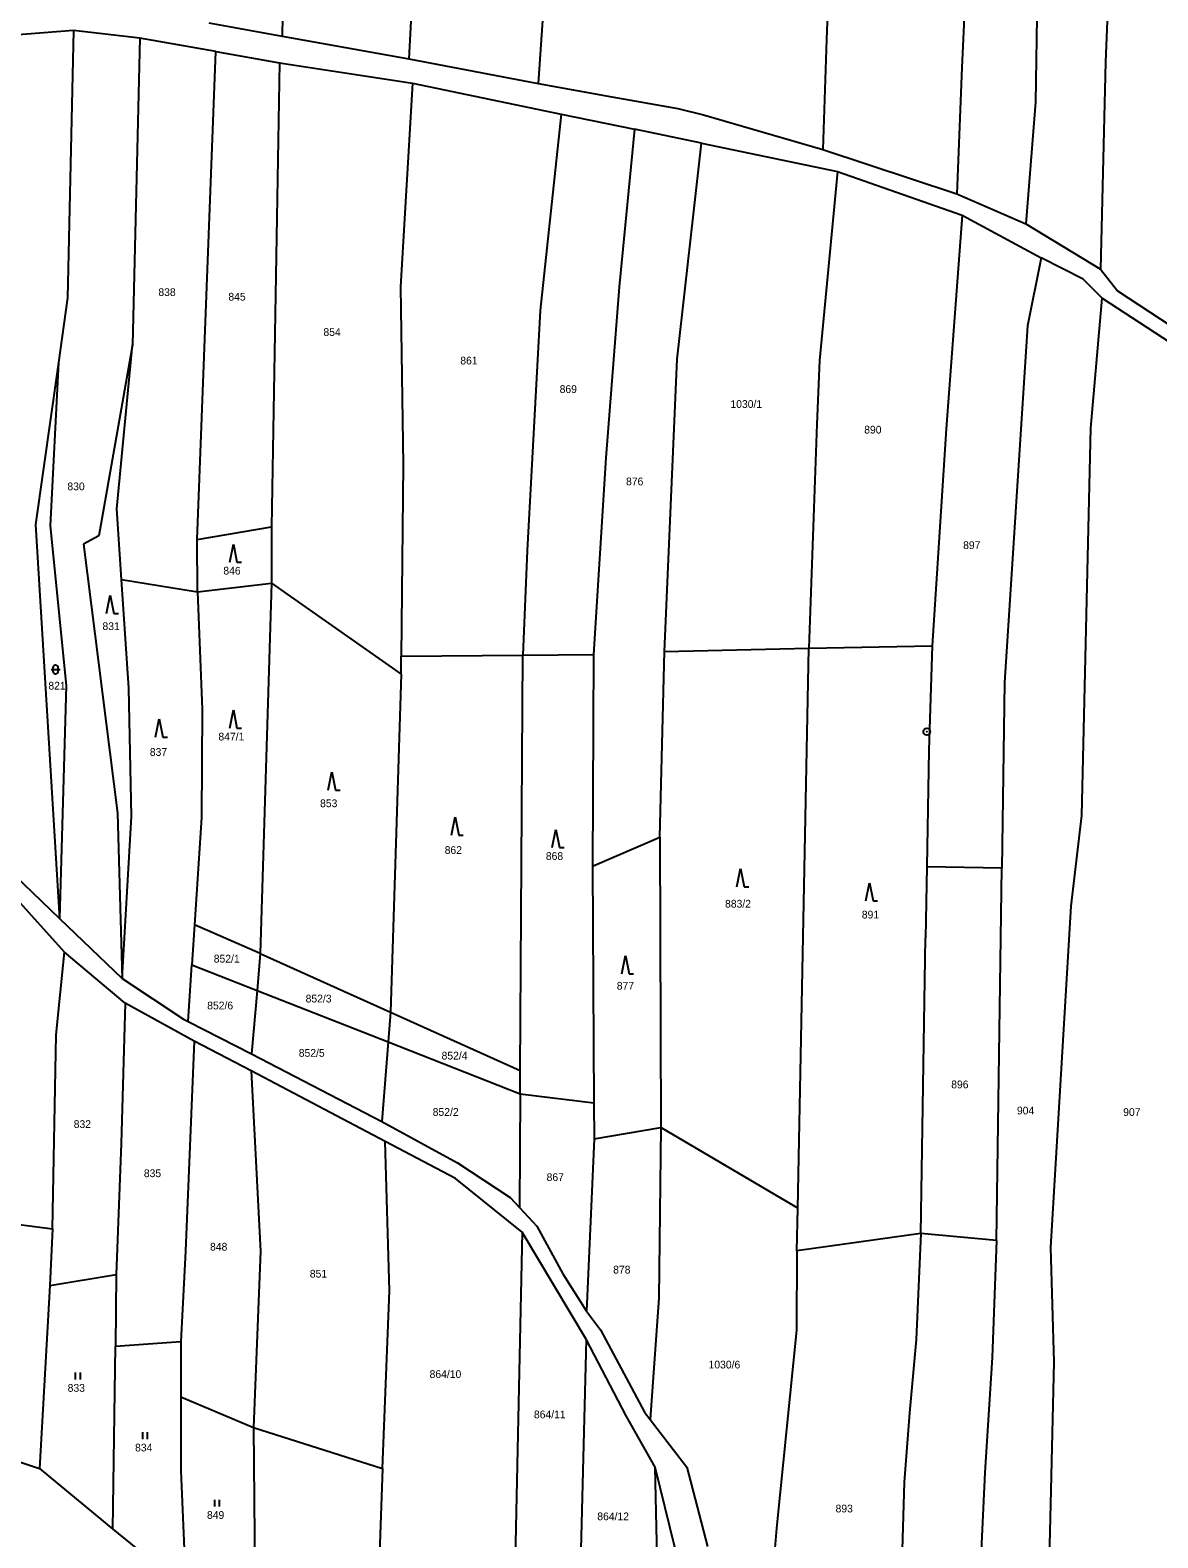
# Model space of a CAD drawing. Extents: x -794142 to -791199, y -1109267 to -1105626.
# Drawn here: x -792888.4 to -792641, y -1108421 to -1108090.1 of the extents above; entities that cross this region are included whole.
import ezdxf

# ---------------------------------------------------------------- set-up
doc = ezdxf.new("R2010")
doc.units = 0
for name, color, linetype in [('Vrstva 1', 7, 'Continuous'), ('Vrstva 14', 7, 'Continuous'), ('Vrstva 23', 7, 'Continuous'), ('Vrstva 28', 7, 'Continuous')]:
    doc.layers.add(name, color=color, linetype=linetype)

msp = doc.modelspace()

# ---------------------------------------------------------------- linework, layer by layer
at = {"layer": 'Vrstva 1'}
for p, q in [((-792665.55, -1107962.36), (-792667.85, -1108105.9)), ((-792830.62, -1107984.08), (-792833.11, -1108091.41)), ((-792710.18, -1107997.92), (-792713.64, -1108092.18)), ((-792800.6, -1108011.76), (-792805.3, -1108096.41)), ((-792771.61, -1108024.99), (-792776.93, -1108101.83)), ((-792680.74, -1108026.56), (-792683.96, -1108098.3)), ((-792650.37, -1108043.61), (-792652.44, -1108097.13)), ((-792849.16, -1108088.53), (-792833.11, -1108091.41)), ((-792878.82, -1108090.18), (-792895.65, -1108091.52)), ((-792878.82, -1108090.18), (-792880.16, -1108148.89)), ((-792864.29, -1108091.85), (-792878.82, -1108090.18)), ((-792864.29, -1108091.85), (-792865.89, -1108159.21)), ((-792847.61, -1108094.83), (-792864.29, -1108091.85)), ((-792833.11, -1108091.41), (-792805.3, -1108096.41)), ((-792851.73, -1108201.91), (-792847.61, -1108094.83)), ((-792847.61, -1108094.83), (-792833.66, -1108097.29)), ((-792713.64, -1108092.18), (-792714.47, -1108116.28)), ((-792833.66, -1108097.29), (-792835.42, -1108199.14)), ((-792833.66, -1108097.29), (-792804.47, -1108101.76)), ((-792805.3, -1108096.41), (-792776.93, -1108101.83)), ((-792683.96, -1108098.3), (-792685.05, -1108126.02)), ((-792652.44, -1108097.13), (-792653.58, -1108142.57)), ((-792804.47, -1108101.76), (-792807.15, -1108146.46)), ((-792804.47, -1108101.76), (-792771.85, -1108108.59)), ((-792776.93, -1108101.83), (-792760.74, -1108104.79)), ((-792760.74, -1108104.79), (-792746.3, -1108107.33)), ((-792771.85, -1108108.59), (-792776.47, -1108151.65)), ((-792771.85, -1108108.59), (-792755.77, -1108111.87)), ((-792746.3, -1108107.33), (-792740.64, -1108108.73)), ((-792667.85, -1108105.9), (-792669.96, -1108132.59)), ((-792755.77, -1108111.87), (-792759.12, -1108146.43)), ((-792741.09, -1108114.9), (-792755.77, -1108111.87)), ((-792740.64, -1108108.73), (-792714.47, -1108116.28)), ((-792746.46, -1108162.29), (-792741.09, -1108114.9)), ((-792741.09, -1108114.9), (-792711.24, -1108121.16)), ((-792714.47, -1108116.28), (-792685.05, -1108126.02)), ((-792711.24, -1108121.16), (-792715.18, -1108162.59)), ((-792711.24, -1108121.16), (-792683.91, -1108130.73)), ((-792685.05, -1108126.02), (-792669.96, -1108132.59)), ((-792683.91, -1108130.73), (-792687.41, -1108177.63)), ((-792683.91, -1108130.73), (-792666.56, -1108140.08)), ((-792669.96, -1108132.59), (-792653.58, -1108142.57)), ((-792666.56, -1108140.08), (-792669.54, -1108154.98)), ((-792657.33, -1108144.76), (-792666.56, -1108140.08)), ((-792653.17, -1108148.97), (-792657.33, -1108144.76)), ((-792653.58, -1108142.57), (-792649.81, -1108147.33)), ((-792807.15, -1108146.46), (-792806.55, -1108185.5)), ((-792759.12, -1108146.43), (-792762.1, -1108183.98)), ((-792649.81, -1108147.33), (-792628.98, -1108161.01)), ((-792880.16, -1108148.89), (-792882.16, -1108163.04)), ((-792776.47, -1108151.65), (-792779.3, -1108204.34)), ((-792655.7, -1108177.43), (-792653.17, -1108148.97)), ((-792653.17, -1108148.97), (-792626.61, -1108166.32)), ((-792669.54, -1108154.98), (-792674.6, -1108233.26)), ((-792865.89, -1108159.21), (-792873.27, -1108201.08)), ((-792869.37, -1108195.13), (-792865.89, -1108159.21)), ((-792882.16, -1108163.04), (-792887.22, -1108198.63)), ((-792882.16, -1108163.04), (-792884, -1108198.88)), ((-792749.22, -1108226.49), (-792746.46, -1108162.29)), ((-792715.18, -1108162.59), (-792715.77, -1108176.59)), ((-792715.77, -1108176.59), (-792717.52, -1108225.72)), ((-792687.41, -1108177.63), (-792690.5, -1108225.21)), ((-792657.64, -1108262.42), (-792655.7, -1108177.43)), ((-792762.1, -1108183.98), (-792764.81, -1108227.16)), ((-792806.55, -1108185.5), (-792806.94, -1108227.47)), ((-792868.32, -1108210.68), (-792869.37, -1108195.13)), ((-792887.22, -1108198.63), (-792881.96, -1108285.08)), ((-792884, -1108198.88), (-792880.45, -1108233.94)), ((-792873.27, -1108201.08), (-792876.63, -1108202.92)), ((-792851.73, -1108201.91), (-792835.42, -1108199.14)), ((-792835.42, -1108199.14), (-792835.42, -1108211.46)), ((-792876.63, -1108202.92), (-792869.23, -1108261.95)), ((-792851.65, -1108213.34), (-792851.73, -1108201.91)), ((-792779.3, -1108204.34), (-792780.3, -1108227.26)), ((-792866.7, -1108234.53), (-792868.32, -1108210.68)), ((-792868.32, -1108210.68), (-792851.65, -1108213.34)), ((-792851.65, -1108213.34), (-792835.42, -1108211.46)), ((-792851.65, -1108213.34), (-792850.66, -1108239.1)), ((-792835.42, -1108211.46), (-792837.88, -1108292.76)), ((-792835.42, -1108211.46), (-792806.94, -1108231.47)), ((-792806.94, -1108227.47), (-792780.3, -1108227.26)), ((-792806.94, -1108231.47), (-792806.94, -1108227.47)), ((-792780.86, -1108318.38), (-792780.3, -1108227.26)), ((-792780.3, -1108227.26), (-792764.81, -1108227.16)), ((-792764.81, -1108227.16), (-792765.01, -1108273.59)), ((-792750.24, -1108267.23), (-792749.22, -1108226.49)), ((-792749.22, -1108226.49), (-792717.52, -1108225.72)), ((-792719.95, -1108348.6), (-792717.52, -1108225.72)), ((-792717.52, -1108225.72), (-792690.5, -1108225.21)), ((-792690.5, -1108225.21), (-792691.22, -1108248.15)), ((-792880.45, -1108233.94), (-792881.96, -1108285.08)), ((-792806.94, -1108231.47), (-792809.35, -1108305.58)), ((-792674.6, -1108233.26), (-792675.2, -1108274.03)), ((-792866.15, -1108262.65), (-792866.7, -1108234.53)), ((-792850.66, -1108239.1), (-792850.8, -1108262.92)), ((-792691.22, -1108248.15), (-792691.67, -1108273.69)), ((-792869.23, -1108261.95), (-792868.2, -1108298.19)), ((-792868.2, -1108298.19), (-792866.15, -1108262.65)), ((-792850.8, -1108262.92), (-792852.32, -1108286.45)), ((-792660.01, -1108282.35), (-792657.64, -1108262.42)), ((-792765.01, -1108273.59), (-792750.24, -1108267.23)), ((-792750.24, -1108267.23), (-792750.02, -1108330.95)), ((-792899.4, -1108268.29), (-792881.96, -1108285.08)), ((-792880.81, -1108292.42), (-792897.89, -1108273.53)), ((-792765.01, -1108273.59), (-792764.68, -1108325.53)), ((-792691.67, -1108273.69), (-792691.94, -1108289.27)), ((-792675.2, -1108274.03), (-792691.67, -1108273.69)), ((-792676.41, -1108355.7), (-792675.2, -1108274.03)), ((-792664.48, -1108357.27), (-792660.01, -1108282.35)), ((-792881.96, -1108285.08), (-792868.2, -1108298.19)), ((-792852.32, -1108286.45), (-792852.88, -1108295.2)), ((-792837.88, -1108292.76), (-792852.32, -1108286.45)), ((-792693, -1108354.18), (-792691.94, -1108289.27)), ((-792882.68, -1108310.58), (-792880.81, -1108292.42)), ((-792867.54, -1108303.62), (-792880.81, -1108292.42)), ((-792837.88, -1108292.76), (-792838.58, -1108300.83)), ((-792837.88, -1108292.76), (-792809.35, -1108305.58)), ((-792853.68, -1108307.68), (-792852.88, -1108295.2)), ((-792852.88, -1108295.2), (-792838.58, -1108300.83)), ((-792868.2, -1108298.19), (-792854.7, -1108307.16)), ((-792867.54, -1108303.62), (-792868.37, -1108334.44)), ((-792852.42, -1108311.98), (-792867.54, -1108303.62)), ((-792838.58, -1108300.83), (-792839.78, -1108314.72)), ((-792838.58, -1108300.83), (-792809.86, -1108312.13)), ((-792854.7, -1108307.16), (-792853.68, -1108307.68)), ((-792809.35, -1108305.58), (-792809.86, -1108312.13)), ((-792809.35, -1108305.58), (-792780.86, -1108318.38)), ((-792853.68, -1108307.68), (-792839.78, -1108314.72)), ((-792883.44, -1108353.15), (-792882.68, -1108310.58)), ((-792852.42, -1108311.98), (-792854.26, -1108358.09)), ((-792839.89, -1108318.51), (-792852.42, -1108311.98)), ((-792809.86, -1108312.13), (-792811.23, -1108329.63)), ((-792809.86, -1108312.13), (-792780.89, -1108323.53)), ((-792839.78, -1108314.72), (-792811.23, -1108329.63)), ((-792839.89, -1108318.51), (-792837.84, -1108358.03)), ((-792810.51, -1108334), (-792839.89, -1108318.51)), ((-792780.89, -1108323.53), (-792780.86, -1108318.38)), ((-792780.89, -1108323.53), (-792781.04, -1108348.46)), ((-792780.89, -1108323.53), (-792764.68, -1108325.53)), ((-792764.68, -1108325.53), (-792764.63, -1108333.43)), ((-792811.23, -1108329.63), (-792794.61, -1108338.65)), ((-792764.63, -1108333.43), (-792766.34, -1108371.22)), ((-792764.63, -1108333.43), (-792750.02, -1108330.95)), ((-792750.02, -1108330.95), (-792750.48, -1108368.33)), ((-792719.95, -1108348.6), (-792750.02, -1108330.95)), ((-792868.37, -1108334.44), (-792869.52, -1108363.21)), ((-792809.53, -1108366.78), (-792810.51, -1108334)), ((-792795.05, -1108342.12), (-792810.51, -1108334)), ((-792794.61, -1108338.65), (-792783.07, -1108346.3)), ((-792780.44, -1108353.88), (-792795.05, -1108342.12)), ((-792783.07, -1108346.3), (-792781.04, -1108348.46)), ((-792781.04, -1108348.46), (-792777.19, -1108352.57)), ((-792720.14, -1108358.01), (-792719.95, -1108348.6)), ((-792901.5, -1108350.78), (-792883.44, -1108353.15)), ((-792883.44, -1108353.15), (-792884.03, -1108365.58)), ((-792777.19, -1108352.57), (-792771.5, -1108363.03)), ((-792780.44, -1108353.88), (-792781.94, -1108425.49)), ((-792766.34, -1108377.52), (-792780.44, -1108353.88)), ((-792693, -1108354.18), (-792720.14, -1108358.01)), ((-792693, -1108354.18), (-792693.97, -1108377.44)), ((-792676.41, -1108355.7), (-792693, -1108354.18)), ((-792676.41, -1108355.7), (-792677.29, -1108381.38)), ((-792854.26, -1108358.09), (-792855.32, -1108377.87)), ((-792837.84, -1108358.03), (-792839.37, -1108396.76)), ((-792720.14, -1108358.01), (-792720.26, -1108375.38)), ((-792663.74, -1108382.44), (-792664.48, -1108357.27)), ((-792884.03, -1108365.58), (-792869.52, -1108363.21)), ((-792869.52, -1108363.21), (-792869.67, -1108378.91)), ((-792771.5, -1108363.03), (-792766.34, -1108371.22)), ((-792884.03, -1108365.58), (-792886.32, -1108405.71)), ((-792811.1, -1108405.72), (-792809.53, -1108366.78)), ((-792750.48, -1108368.33), (-792752.37, -1108394.99)), ((-792766.34, -1108371.22), (-792763.25, -1108375.3)), ((-792763.25, -1108375.3), (-792753.62, -1108393.36)), ((-792720.26, -1108375.38), (-792724.65, -1108418.81)), ((-792870.21, -1108419.08), (-792869.67, -1108378.91)), ((-792869.67, -1108378.91), (-792855.32, -1108377.87)), ((-792855.32, -1108377.87), (-792855.32, -1108390.02)), ((-792767.58, -1108426.45), (-792766.34, -1108377.52)), ((-792757.64, -1108394.2), (-792766.34, -1108377.52)), ((-792693.97, -1108377.44), (-792695.46, -1108393.53)), ((-792677.29, -1108381.38), (-792678.93, -1108406.65)), ((-792664.48, -1108413.59), (-792663.74, -1108382.44)), ((-792855.32, -1108390.02), (-792855.33, -1108406.24)), ((-792855.32, -1108390.02), (-792839.37, -1108396.76)), ((-792751.22, -1108405.47), (-792757.64, -1108394.2)), ((-792753.62, -1108393.36), (-792752.37, -1108394.99)), ((-792752.37, -1108394.99), (-792744.34, -1108405.47)), ((-792695.46, -1108393.53), (-792696.65, -1108408.73)), ((-792839.37, -1108396.76), (-792838.98, -1108444.42)), ((-792839.37, -1108396.76), (-792811.1, -1108405.72)), ((-792903.82, -1108400.01), (-792886.32, -1108405.71)), ((-792886.32, -1108405.71), (-792870.21, -1108419.08)), ((-792855.33, -1108406.24), (-792854.24, -1108432)), ((-792811.1, -1108405.72), (-792811.91, -1108429.71)), ((-792750.3, -1108447.92), (-792751.22, -1108405.47)), ((-792745.94, -1108427.17), (-792751.22, -1108405.47)), ((-792744.34, -1108405.47), (-792739.76, -1108422.84)), ((-792696.65, -1108408.73), (-792697.7, -1108444.29)), ((-792678.93, -1108406.65), (-792680.27, -1108435.34)), ((-792665.97, -1108475.58), (-792664.48, -1108413.59)), ((-792870.21, -1108419.08), (-792854.24, -1108432)), ((-792724.65, -1108418.81), (-792727.1, -1108448.02))]:
    msp.add_line(p, q, dxfattribs=at)
at = {"layer": 'Vrstva 23'}
for p, q in [((-792844.59, -1108206.88), (-792843.79, -1108202.88)), ((-792843.79, -1108202.88), (-792842.99, -1108206.88)), ((-792842.99, -1108206.88), (-792841.99, -1108206.88)), ((-792871.6, -1108218.12), (-792870.8, -1108214.12)), ((-792870.8, -1108214.12), (-792870, -1108218.12)), ((-792870, -1108218.12), (-792869, -1108218.12)), ((-792883.79, -1108230.41), (-792881.79, -1108230.41)), ((-792883.29, -1108229.81), (-792883.19, -1108229.61)), ((-792883.29, -1108231.01), (-792883.29, -1108229.81)), ((-792883.19, -1108231.21), (-792883.29, -1108231.01)), ((-792883.19, -1108229.61), (-792883.09, -1108229.51)), ((-792883.09, -1108229.51), (-792882.89, -1108229.41)), ((-792882.89, -1108229.41), (-792882.69, -1108229.41)), ((-792882.69, -1108229.41), (-792882.49, -1108229.51)), ((-792882.49, -1108229.51), (-792882.39, -1108229.61)), ((-792882.39, -1108229.61), (-792882.29, -1108229.81)), ((-792882.29, -1108231.01), (-792882.39, -1108231.21)), ((-792882.29, -1108229.81), (-792882.29, -1108231.01)), ((-792883.09, -1108231.31), (-792883.19, -1108231.21)), ((-792882.89, -1108231.41), (-792883.09, -1108231.31)), ((-792882.69, -1108231.41), (-792882.89, -1108231.41)), ((-792882.49, -1108231.31), (-792882.69, -1108231.41)), ((-792882.39, -1108231.21), (-792882.49, -1108231.31)), ((-792844.59, -1108243.29), (-792843.79, -1108239.29)), ((-792843.79, -1108239.29), (-792842.99, -1108243.29)), ((-792860.85, -1108245.24), (-792860.05, -1108241.24)), ((-792860.05, -1108241.24), (-792859.25, -1108245.24)), ((-792842.99, -1108243.29), (-792841.99, -1108243.29)), ((-792859.25, -1108245.24), (-792858.25, -1108245.24)), ((-792822.99, -1108256.86), (-792822.19, -1108252.86)), ((-792822.19, -1108252.86), (-792821.39, -1108256.86)), ((-792821.39, -1108256.86), (-792820.39, -1108256.86)), ((-792795.95, -1108266.77), (-792795.15, -1108262.77)), ((-792795.15, -1108262.77), (-792794.35, -1108266.77)), ((-792794.35, -1108266.77), (-792793.35, -1108266.77)), ((-792773.84, -1108269.5), (-792773.04, -1108265.5)), ((-792773.04, -1108265.5), (-792772.24, -1108269.5)), ((-792772.24, -1108269.5), (-792771.24, -1108269.5)), ((-792733.33, -1108278.11), (-792732.53, -1108274.11)), ((-792732.53, -1108274.11), (-792731.73, -1108278.11)), ((-792705.05, -1108281.21), (-792704.25, -1108277.21)), ((-792704.25, -1108277.21), (-792703.45, -1108281.21)), ((-792731.73, -1108278.11), (-792730.73, -1108278.11)), ((-792703.45, -1108281.21), (-792702.45, -1108281.21)), ((-792758.59, -1108297.19), (-792757.79, -1108293.19)), ((-792757.79, -1108293.19), (-792756.99, -1108297.19)), ((-792756.99, -1108297.19), (-792755.99, -1108297.19)), ((-792878.42, -1108386.21), (-792878.42, -1108384.71)), ((-792877.42, -1108384.71), (-792877.42, -1108386.21)), ((-792863.66, -1108399.3), (-792863.66, -1108397.8)), ((-792862.66, -1108397.8), (-792862.66, -1108399.3)), ((-792847.88, -1108414.1), (-792847.88, -1108412.6)), ((-792846.88, -1108412.6), (-792846.88, -1108414.1))]:
    msp.add_line(p, q, dxfattribs=at)
at = {"layer": 'Vrstva 28'}
for radius in [0.75, 0.01]:
    msp.add_circle((-792691.67, -1108244.06), radius, dxfattribs=at)

# ---------------------------------------------------------------- texts
at = {"layer": 'Vrstva 14'}
for s, p in [('838', (-792860.236, -1108148.47)), ('845', (-792844.879, -1108149.47)), ('854', (-792824.029, -1108157.22)), ('861', (-792794, -1108163.48)), ('869', (-792772.207, -1108169.74)), ('1030/1', (-792734.745, -1108173.02)), ('890', (-792705.396, -1108178.64)), ('830', (-792880.196, -1108191.09)), ('876', (-792757.643, -1108190)), ('897', (-792683.693, -1108203.98)), ('846', (-792845.982, -1108209.58)), ('831', (-792872.5, -1108221.76)), ('821', (-792884.37, -1108234.82)), ('847/1', (-792847.065, -1108245.99)), ('837', (-792862.113, -1108249.37)), ('853', (-792824.763, -1108260.63)), ('862', (-792797.426, -1108270.89)), ('868', (-792775.236, -1108272.2)), ('883/2', (-792735.92, -1108282.67)), ('891', (-792705.92, -1108285.05)), ('852/1', (-792848.089, -1108294.72)), ('877', (-792759.67, -1108300.67)), ('852/6', (-792849.526, -1108305)), ('852/3', (-792827.936, -1108303.48)), ('852/5', (-792829.442, -1108315.4)), ('852/4', (-792798.112, -1108316)), ('896', (-792686.307, -1108322.31)), ('852/2', (-792800.056, -1108328.36)), ('904', (-792671.892, -1108328.05)), ('907', (-792648.582, -1108328.38)), ('832', (-792878.806, -1108331.02)), ('835', (-792863.423, -1108341.81)), ('867', (-792775.073, -1108342.67)), ('848', (-792848.902, -1108357.93)), ('851', (-792827.016, -1108363.85)), ('878', (-792760.463, -1108362.96)), ('1030/6', (-792739.542, -1108383.79)), ('864/10', (-792800.738, -1108385.88)), ('833', (-792880.137, -1108388.91)), ('864/11', (-792777.852, -1108394.73)), ('834', (-792865.352, -1108402)), ('849', (-792849.572, -1108416.8)), ('864/12', (-792763.949, -1108417.1)), ('893', (-792711.677, -1108415.38))]:
    msp.add_text(s, height=1.7, dxfattribs=at).set_placement(p)

doc.saveas('drawing.dxf')
